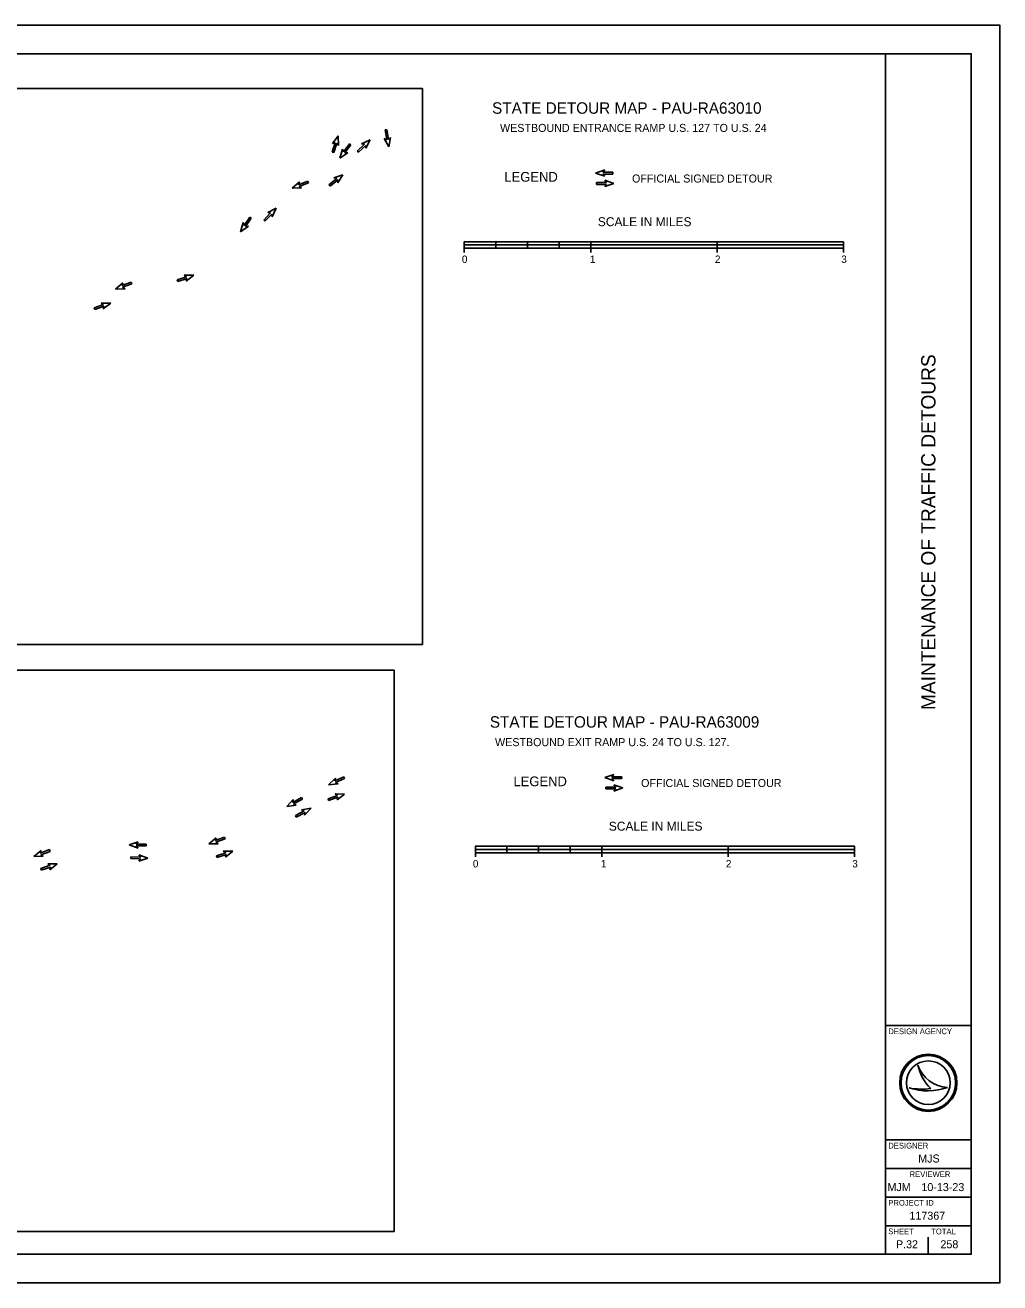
# Model space of a CAD drawing. Extents: x -8327 to 680, y -1188960 to 440.
# Drawn here: x 339.2 to 680, y 0 to 440 of the extents above; entities that cross this region are included whole.
import ezdxf

# ---------------------------------------------------------------- set-up
doc = ezdxf.new("R2010")
doc.units = 0
for name, color, linetype in [('GM_X_County', 7, 'Continuous'), ('GM_X_Minor_Lake', 7, 'Continuous'), ('GM_X_Minor_Lake_Text', 7, 'Continuous'), ('GM_X_Minor_River', 7, 'Continuous'), ('GM_X_Minor_River_Text', 7, 'Continuous')]:
    doc.layers.add(name, color=color, linetype=linetype)

msp = doc.modelspace()

# ---------------------------------------------------------------- linework, layer by layer
at = {"layer": 'GM_X_County'}
msp.add_lwpolyline([(0, 0), (680, 0), (680, 440), (0, 440)], close=True, dxfattribs=at)
at = {"layer": 'GM_X_Minor_Lake'}
for p, q in [((492.76, 364.21), (492.76, 360.48)), ((492.76, 361.97), (503.81, 361.97)), ((498.84, 364.21), (503.81, 364.21)), ((498.84, 363.09), (503.81, 363.09)), ((503.81, 364.21), (503.81, 361.97)), ((503.81, 364.21), (514.85, 364.21)), ((509.88, 363.09), (514.85, 363.09)), ((509.88, 361.97), (514.85, 361.97)), ((514.85, 364.21), (514.85, 361.97)), ((514.85, 361.97), (525.9, 361.97)), ((520.93, 364.21), (525.9, 364.21)), ((520.93, 363.09), (525.9, 363.09)), ((525.9, 364.21), (525.9, 361.97)), ((525.9, 364.21), (536.94, 364.21)), ((525.9, 363.09), (530.87, 363.09)), ((525.9, 361.97), (530.87, 361.97)), ((536.94, 360.48), (536.94, 364.21)), ((536.94, 361.97), (581.12, 361.97)), ((561.23, 364.21), (581.12, 364.21)), ((561.23, 363.09), (581.12, 363.09)), ((581.12, 360.48), (581.12, 364.21)), ((581.12, 364.21), (625.3, 364.21)), ((605.41, 363.09), (625.3, 363.09)), ((605.41, 361.97), (625.3, 361.97)), ((625.3, 360.48), (625.3, 364.21)), ((496.61, 152.73), (496.61, 149)), ((496.61, 150.49), (507.65, 150.49)), ((502.68, 152.73), (507.65, 152.73)), ((502.68, 151.61), (507.65, 151.61)), ((507.65, 152.73), (507.65, 150.49)), ((507.65, 152.73), (518.7, 152.73)), ((513.72, 151.61), (518.7, 151.61)), ((513.72, 150.49), (518.7, 150.49)), ((518.7, 152.73), (518.7, 150.49)), ((518.7, 150.49), (529.74, 150.49)), ((524.77, 152.73), (529.74, 152.73)), ((524.77, 151.61), (529.74, 151.61)), ((529.74, 152.73), (529.74, 150.49)), ((529.74, 152.73), (540.79, 152.73)), ((529.74, 151.61), (534.72, 151.61)), ((529.74, 150.49), (534.72, 150.49)), ((540.79, 149), (540.79, 152.73)), ((540.79, 150.49), (584.97, 150.49)), ((565.07, 152.73), (584.97, 152.73)), ((565.07, 151.61), (584.97, 151.61)), ((584.97, 149), (584.97, 152.73)), ((584.97, 152.73), (629.15, 152.73)), ((609.25, 151.61), (629.15, 151.61)), ((609.25, 150.49), (629.15, 150.49)), ((629.15, 149), (629.15, 152.73))]:
    msp.add_line(p, q, dxfattribs=at)
for points in [[(58.11, 417.89), (478.11, 417.89), (478.11, 223.38), (58.11, 223.38)], [(503.81, 363.09), (492.76, 363.09), (492.76, 364.21), (503.81, 364.21)], [(503.81, 363.09), (514.85, 363.09), (514.85, 361.97), (503.81, 361.97)], [(514.85, 363.09), (525.9, 363.09), (525.9, 364.21), (514.85, 364.21)], [(525.9, 363.09), (536.94, 363.09), (536.94, 361.97), (525.9, 361.97)], [(536.94, 363.09), (581.12, 363.09), (581.12, 364.21), (536.94, 364.21)], [(581.12, 363.09), (625.3, 363.09), (625.3, 361.97), (581.12, 361.97)], [(58.11, 214.39), (468.2, 214.39), (468.2, 18), (58.11, 18)], [(507.65, 151.61), (496.61, 151.61), (496.61, 152.73), (507.65, 152.73)], [(507.65, 151.61), (518.7, 151.61), (518.7, 150.49), (507.65, 150.49)], [(518.7, 151.61), (529.74, 151.61), (529.74, 152.73), (518.7, 152.73)], [(529.74, 151.61), (540.79, 151.61), (540.79, 150.49), (529.74, 150.49)], [(540.79, 151.61), (584.97, 151.61), (584.97, 152.73), (540.79, 152.73)], [(584.96, 151.61), (629.15, 151.61), (629.15, 150.49), (584.96, 150.49)]]:
    msp.add_lwpolyline(points, close=True, dxfattribs=at)
at = {"layer": 'GM_X_Minor_Lake_Text'}
for p, q in [((651.35, 76.19), (651.35, 76.19)), ((648.34, 68.19), (648.34, 68.19)), ((655, 70), (655, 70)), ((661.75, 68.37), (661.75, 68.37)), ((647.5, 13.5), (647.5, 13.5)), ((655, 10), (655, 16))]:
    msp.add_line(p, q, dxfattribs=at)
for radius in [10, 9.54, 9.54, 7.64]:
    msp.add_circle((655, 70), radius, dxfattribs=at)
for centre, radius, start, end in [((662.32, 79.95), 11.6, 198.9257, 198.9319), ((666.93, 79.4), 15.91, 191.6379, 191.6421), ((662.32, 79.95), 11.6, 198.9319, 267.1657), ((666.93, 79.4), 15.91, 191.6421, 226.0947), ((654.79, 87.4), 20.26, 251.4576, 290.0832), ((652.96, 93.09), 25.32, 259.4964, 259.4995), ((654.79, 87.4), 20.26, 251.4527, 251.4576), ((652.96, 93.09), 25.32, 259.4995, 276.6672)]:
    msp.add_arc(centre, radius, start, end, dxfattribs=at)
at = {"layer": 'GM_X_Minor_River'}
for p, q in [((446.69, 398.57), (448.7, 401.25)), ((448.7, 401.25), (448.78, 397.9)), ((465.07, 403.32), (465.69, 403.43)), ((465.63, 399.89), (465.07, 403.32)), ((465.69, 403.43), (466.25, 399.99)), ((466.25, 399.99), (466.92, 400.74)), ((466.92, 400.74), (466.35, 397.44)), ((446.57, 395.62), (447.62, 398.93)), ((447.62, 398.93), (446.69, 398.57)), ((448.23, 398.74), (447.17, 395.43)), ((448.78, 397.9), (448.23, 398.74)), ((449.2, 393.46), (450.22, 396.65)), ((450.22, 396.65), (450.47, 395.68)), ((450.47, 395.68), (452.56, 398.46)), ((453.06, 398.08), (450.97, 395.3)), ((452.56, 398.46), (453.06, 398.08)), ((455.34, 395.96), (457.83, 398.39)), ((458.27, 397.94), (455.78, 395.51)), ((456.83, 398.51), (459.87, 399.93)), ((457.83, 398.39), (456.83, 398.51)), ((458.37, 396.94), (458.27, 397.94)), ((459.87, 399.93), (458.37, 396.94)), ((466.35, 397.44), (464.75, 400.39)), ((464.75, 400.39), (465.63, 399.89)), ((447.17, 395.43), (446.57, 395.62)), ((451.98, 395.33), (449.2, 393.46)), ((450.97, 395.3), (451.98, 395.33)), ((455.78, 395.51), (455.34, 395.96)), ((447.16, 386.53), (450.31, 387.66)), ((450.31, 387.66), (448.53, 384.82)), ((538.66, 388.23), (541.83, 389.33)), ((541.83, 387.14), (538.66, 388.23)), ((541.83, 389.33), (541.2, 388.55)), ((541.2, 388.55), (544.68, 388.55)), ((544.68, 387.92), (541.2, 387.92)), ((541.2, 387.92), (541.83, 387.14)), ((544.68, 388.55), (544.68, 387.92)), ((432.52, 382.97), (435.07, 385.14)), ((435.86, 383.09), (432.52, 382.97)), ((434.76, 384.18), (438, 385.44)), ((435.07, 385.14), (434.76, 384.18)), ((438.23, 384.85), (434.99, 383.59)), ((434.99, 383.59), (435.86, 383.09)), ((438, 385.44), (438.23, 384.85)), ((445.43, 384.14), (448.14, 386.32)), ((445.82, 383.65), (445.43, 384.14)), ((448.54, 385.83), (445.82, 383.65)), ((448.14, 386.32), (447.16, 386.53)), ((448.53, 384.82), (448.54, 385.83)), ((539.03, 384.31), (539.03, 384.94)), ((539.03, 384.94), (542.51, 384.94)), ((542.51, 384.31), (539.03, 384.31)), ((542.51, 384.94), (541.88, 385.72)), ((541.88, 385.72), (545.04, 384.63)), ((545.04, 384.63), (541.88, 383.53)), ((541.88, 383.53), (542.51, 384.31)), ((422.61, 371.83), (425.02, 374.34)), ((424.02, 374.43), (427.01, 375.94)), ((425.02, 374.34), (424.02, 374.43)), ((427.01, 375.94), (425.6, 372.9)), ((414.53, 367.71), (415.45, 370.93)), ((417.25, 369.67), (414.53, 367.71)), ((415.45, 370.93), (415.73, 369.96)), ((415.73, 369.96), (417.73, 372.81)), ((418.25, 372.45), (416.24, 369.6)), ((416.24, 369.6), (417.25, 369.67)), ((417.73, 372.81), (418.25, 372.45)), ((423.06, 371.39), (422.61, 371.83)), ((425.48, 373.9), (423.06, 371.39)), ((425.6, 372.9), (425.48, 373.9)), ((395.63, 351.98), (394.78, 352.52)), ((394.78, 352.52), (398.13, 352.5)), ((398.13, 352.5), (395.49, 350.44)), ((370.8, 347.68), (373.37, 349.82)), ((374.14, 347.77), (370.8, 347.68)), ((373.05, 348.87), (376.31, 350.09)), ((373.37, 349.82), (373.05, 348.87)), ((376.54, 349.5), (373.28, 348.28)), ((373.28, 348.28), (374.14, 347.77)), ((376.31, 350.09), (376.54, 349.5)), ((392.34, 350.86), (395.63, 351.98)), ((392.54, 350.26), (392.34, 350.86)), ((395.84, 351.38), (392.54, 350.26)), ((395.49, 350.44), (395.84, 351.38)), ((363.35, 341.14), (366.64, 342.26)), ((363.55, 340.54), (363.35, 341.14)), ((366.85, 341.66), (363.55, 340.54)), ((366.64, 342.26), (365.79, 342.79)), ((365.79, 342.79), (369.14, 342.78)), ((369.14, 342.78), (366.5, 340.71)), ((366.5, 340.71), (366.85, 341.66)), ((445.29, 174.27), (447.73, 176.57)), ((447.47, 175.6), (450.65, 177.02)), ((447.73, 176.57), (447.47, 175.6)), ((450.91, 176.44), (447.73, 175.02)), ((450.65, 177.02), (450.91, 176.44)), ((541.84, 176.75), (545, 177.84)), ((545, 175.65), (541.84, 176.75)), ((545, 177.84), (544.37, 177.06)), ((544.37, 177.06), (547.85, 177.06)), ((547.85, 176.43), (544.37, 176.43)), ((544.37, 176.43), (545, 175.65)), ((547.85, 177.06), (547.85, 176.43)), ((448.63, 174.56), (445.29, 174.27)), ((447.73, 175.02), (448.63, 174.56)), ((542.2, 172.82), (542.2, 173.45)), ((542.2, 173.45), (545.68, 173.45)), ((545.68, 172.82), (542.2, 172.82)), ((545.68, 173.45), (545.05, 174.24)), ((545.05, 174.24), (548.22, 173.14)), ((548.22, 173.14), (545.05, 172.04)), ((545.05, 172.04), (545.68, 172.82)), ((430.7, 166.63), (432.97, 169.09)), ((432.78, 168.1), (435.85, 169.75)), ((432.97, 169.09), (432.78, 168.1)), ((436.15, 169.2), (433.08, 167.55)), ((433.08, 167.55), (434.01, 167.16)), ((435.85, 169.75), (436.15, 169.2)), ((445.1, 169.38), (448.4, 170.5)), ((445.3, 168.78), (445.1, 169.38)), ((448.6, 169.9), (445.3, 168.78)), ((448.4, 170.5), (447.55, 171.04)), ((447.55, 171.04), (450.89, 171.01)), ((450.89, 171.01), (448.25, 168.96)), ((448.25, 168.96), (448.6, 169.9)), ((434.01, 167.16), (430.7, 166.63)), ((433.7, 163.48), (436.77, 165.12)), ((434, 162.92), (433.7, 163.48)), ((437.07, 164.56), (434, 162.92)), ((435.84, 165.51), (439.15, 166.03)), ((436.77, 165.12), (435.84, 165.51)), ((439.15, 166.03), (436.88, 163.57)), ((436.88, 163.57), (437.07, 164.56)), ((375.53, 153.19), (378.69, 154.28)), ((378.69, 154.28), (378.06, 153.5)), ((403.37, 153.54), (405.95, 155.68)), ((405.63, 154.72), (408.89, 155.94)), ((405.95, 155.68), (405.63, 154.72)), ((409.11, 155.35), (405.85, 154.13)), ((405.85, 154.13), (406.72, 153.62)), ((408.89, 155.94), (409.11, 155.35)), ((342.19, 149.14), (344.77, 151.28)), ((344.45, 150.32), (347.71, 151.55)), ((344.77, 151.28), (344.45, 150.32)), ((347.93, 150.95), (344.67, 149.73)), ((344.67, 149.73), (345.54, 149.22)), ((347.71, 151.55), (347.93, 150.95)), ((378.69, 152.08), (375.53, 153.19)), ((378.06, 153.5), (381.54, 153.49)), ((381.54, 152.86), (378.06, 152.87)), ((378.06, 152.87), (378.69, 152.08)), ((379.61, 148.97), (378.99, 149.77)), ((378.99, 149.77), (382.13, 148.61)), ((381.54, 153.49), (381.54, 152.86)), ((406.72, 153.62), (403.37, 153.54)), ((406.05, 149.37), (409.34, 150.49)), ((409.55, 149.89), (406.25, 148.77)), ((409.34, 150.49), (408.49, 151.02)), ((408.49, 151.02), (411.84, 151)), ((411.84, 151), (409.2, 148.94)), ((409.2, 148.94), (409.55, 149.89)), ((345.54, 149.22), (342.19, 149.14)), ((344.64, 144.96), (347.94, 146.08)), ((348.14, 145.48), (344.85, 144.36)), ((347.94, 146.08), (347.09, 146.62)), ((347.09, 146.62), (350.44, 146.59)), ((350.44, 146.59), (347.79, 144.54)), ((347.79, 144.54), (348.14, 145.48)), ((376.11, 148.41), (376.13, 149.04)), ((379.59, 148.34), (376.11, 148.41)), ((376.13, 149.04), (379.61, 148.97)), ((382.13, 148.61), (378.95, 147.57)), ((378.95, 147.57), (379.59, 148.34)), ((406.25, 148.77), (406.05, 149.37)), ((344.85, 144.36), (344.64, 144.96))]:
    msp.add_line(p, q, dxfattribs=at)
at = {"layer": 'GM_X_Minor_River_Text'}
for p, q in [((640, 10), (640, 430)), ((640, 90), (670, 90)), ((640, 50), (670, 50)), ((640, 40), (670, 40)), ((640, 30), (670, 30)), ((640, 20), (670, 20))]:
    msp.add_line(p, q, dxfattribs=at)
msp.add_lwpolyline([(30, 430), (670, 430), (670, 10), (30, 10)], close=True, dxfattribs=at)

# ---------------------------------------------------------------- texts
at = {"layer": 'GM_X_Minor_Lake'}
for s, height, p in [('WESTBOUND ENTRANCE RAMP U.S. 127 TO U.S. 24 ', 2.8, (505.25, 402.65)), ('SCALE IN MILES', 3.125, (539.45, 369.68)), ('0', 2.6, (491.91, 356.81)), ('1', 2.6, (536.65, 356.81)), ('2', 2.6, (580.38, 356.81)), ('3', 2.6, (624.56, 356.81)), ('WESTBOUND EXIT RAMP U.S. 24 TO U.S. 127.', 2.8, (503.5, 187.76)), ('SCALE IN MILES', 3.125, (543.29, 158.2)), ('0', 2.6, (495.75, 145.33)), ('1', 2.6, (540.5, 145.33)), ('2', 2.6, (584.22, 145.33)), ('3', 2.6, (628.41, 145.33))]:
    msp.add_text(s, height=height, dxfattribs=at).set_placement(p)
at = {"layer": 'GM_X_Minor_Lake_Text'}
for s, height, p in [('STATE DETOUR MAP - PAU-RA63010', 4, (502.46, 409.01)), ('LEGEND', 3.4, (506.75, 385.23)), ('OFFICIAL SIGNED DETOUR', 2.8, (551.4, 384.95)), ('STATE DETOUR MAP - PAU-RA63009', 4, (501.67, 194.23)), ('LEGEND', 3.4, (509.93, 173.74)), ('OFFICIAL SIGNED DETOUR', 2.8, (554.57, 173.46)), ('DESIGN AGENCY', 2, (641, 87)), ('DESIGNER', 2, (641, 47)), ('MJS', 2.8, (651.48, 42.1)), ('REVIEWER', 2, (648.44, 37)), ('MJM', 2.8, (640.71, 32.1)), ('10-13-23', 2.8, (652.58, 32.1)), ('PROJECT ID', 2, (641, 27)), ('117367', 2.8, (648.4, 22.1)), ('SHEET', 2, (641, 17)), ('TOTAL', 2, (656, 17)), ('P.32', 2.8, (643.69, 12.1)), ('258', 2.8, (659.24, 12.1))]:
    msp.add_text(s, height=height, dxfattribs=at).set_placement(p)
msp.add_text('MAINTENANCE OF TRAFFIC DETOURS', height=5, rotation=90, dxfattribs=at).set_placement((657.5, 200.41))

doc.saveas('drawing.dxf')
